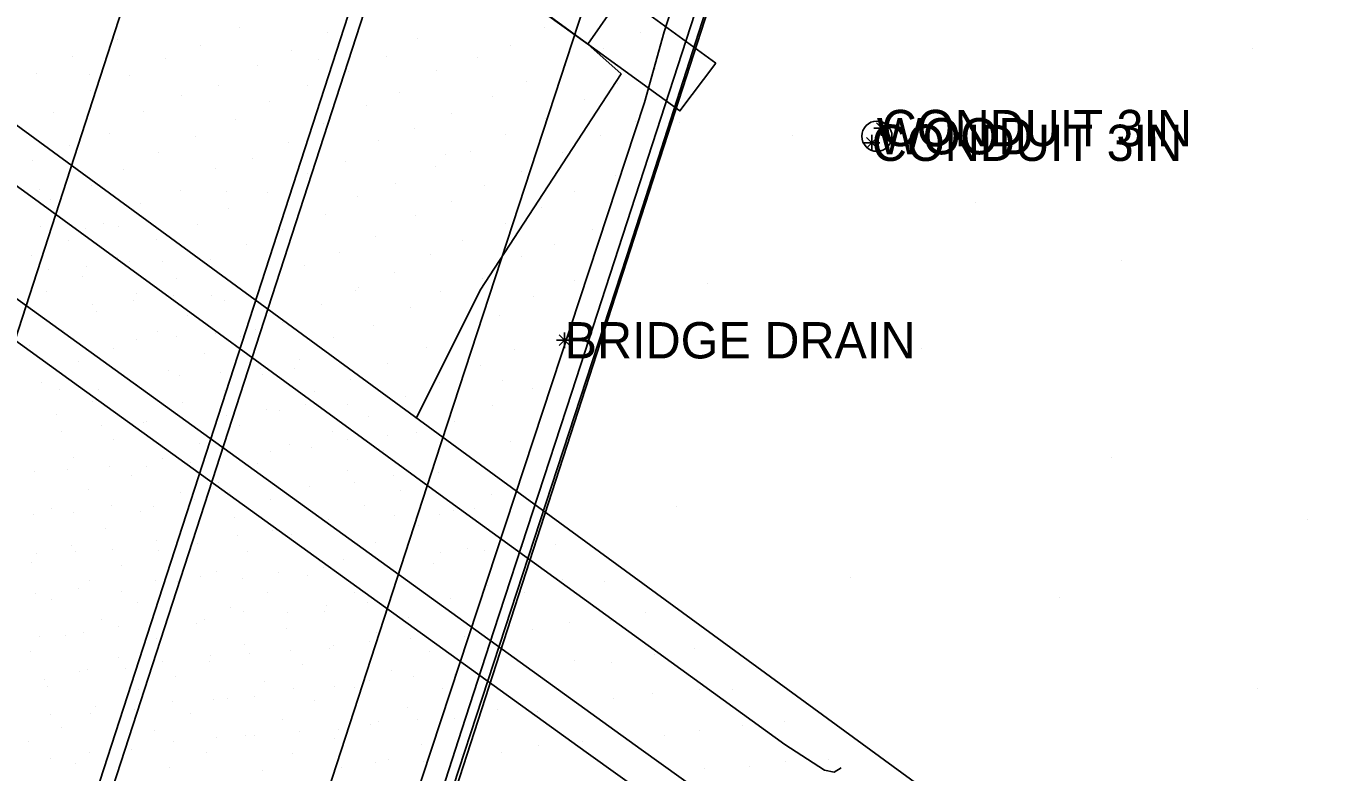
# Model space of a CAD drawing. Extents: x 0 to 1739264, y 0 to 465304.
# Drawn here: x 1738821.1 to 1738885.4, y 464600.2 to 464637.2 of the extents above; entities that cross this region are included whole.
import ezdxf

# ---------------------------------------------------------------- set-up
doc = ezdxf.new("R2010")
doc.units = 0
for name, color, linetype in [('Default', 7, 'Continuous'), ('S_Ground_SpotElevation', 7, 'Continuous'), ('S_Misc_MiscItems', 7, 'Continuous'), ('S_Terrain_Boundary', 7, 'Continuous'), ('S_Terrain_Flow_Arrows', 7, 'Continuous'), ('S_Terrain_Holes', 7, 'Continuous'), ('S_Terrain_Imported_Contours', 7, 'Continuous'), ('S_Terrain_Low_Points', 7, 'Continuous'), ('S_Terrain_Major_Contours_Label', 7, 'Continuous'), ('S_Terrain_Minor_Contours', 7, 'Continuous'), ('S_Terrain_Spots', 7, 'Continuous'), ('S_Terrain_Triangles', 7, 'Continuous'), ('S_Terrain_XSC', 7, 'Continuous'), ('S_Text', 7, 'Continuous'), ('S_Traffic_Posts', 7, 'Continuous')]:
    doc.layers.add(name, color=color, linetype=linetype)

# ---------------------------------------------------------------- blocks, each defined once
blk = doc.blocks.new('POINT_DISPLAY')
at = {"layer": 'Default'}
blk.add_line((0, 0), (0, 0), dxfattribs=at)

msp = doc.modelspace()

# ---------------------------------------------------------------- linework, layer by layer
at = {"layer": 'S_Misc_MiscItems'}
for p, q in [((1738863.757081, 464631.874419), (1738863.232919, 464632.398581)), ((1738863.757081, 464632.398581), (1738863.232919, 464631.874419)), ((1738863.495, 464632.529425), (1738863.495, 464631.743575)), ((1738863.271081, 464631.142519), (1738862.746919, 464631.666681)), ((1738863.271081, 464631.666681), (1738862.746919, 464631.142519)), ((1738863.009, 464631.797525), (1738863.009, 464631.011675)), ((1738863.887925, 464632.1365), (1738863.102075, 464632.1365)), ((1738863.401925, 464631.4046), (1738862.616075, 464631.4046)), ((1738847.785, 464622.004625), (1738847.785, 464621.218775)), ((1738848.177925, 464621.6117), (1738847.392075, 464621.6117)), ((1738848.047081, 464621.349619), (1738847.522919, 464621.873781)), ((1738848.047081, 464621.873781), (1738847.522919, 464621.349619))]:
    msp.add_line(p, q, dxfattribs=at)
at = {"layer": 'S_Terrain_Boundary'}
msp.add_lwpolyline([(1738439.271413, 464900.197601), (1738492.404409, 464861.888198), (1738543.326406, 464825.027297), (1738587.987508, 464792.577201), (1738643.601995, 464752.008903), (1738684.834997, 464722.042197), (1738725.906102, 464692.517997), (1738772.431699, 464658.71659), (1738810.132402, 464631.254401), (1738851.5753, 464601.325202), (1738896.7613, 464568.902991), (1738947.229398, 464532.229499), (1738988.834096, 464501.959205), (1739034.470907, 464468.655585), (1739109.710805, 464413.704902), (1739191.418111, 464354.569221)], dxfattribs=at)
at = {"layer": 'S_Terrain_Flow_Arrows'}
msp.add_lwpolyline([(1738537.8915, 464837.651298), (1738554.679006, 464823.736503), (1738571.817098, 464809.695602), (1738604.832906, 464785.812995), (1738647.717305, 464754.6706), (1738693.440099, 464721.453605), (1738721.065099, 464701.443504), (1738755.298902, 464676.469901), (1738784.46756, 464655.434135), (1738807.545301, 464638.717994), (1738821.158399, 464628.894904), (1738841.6217, 464613.944495), (1738858.6917, 464601.566993), (1738860.6704, 464600.29029), (1738861.1426, 464600.200813), (1738861.4941, 464600.40879)], dxfattribs=at)
at = {"layer": 'S_Terrain_Holes'}
msp.add_lwpolyline([(1738440.753408, 464902.4178), (1738477.708303, 464875.6944), (1738495.304403, 464867.276199), (1738520.483205, 464854.988197), (1738531.014211, 464849.447196), (1738541.85439, 464843.616599), (1738555.182912, 464833.824599), (1738566.262288, 464820.809898), (1738575.120687, 464811.715797), (1738599.964589, 464792.622993), (1738652.316198, 464754.776099), (1738717.522497, 464707.258094), (1738763.349103, 464673.881202), (1738798.761701, 464648.314307), (1738844.3003, 464614.942512), (1738868.1803, 464597.462104), (1738886.0282, 464581.007392), (1738908.3057, 464562.901496), (1738954.7096, 464529.656501), (1739018.291097, 464483.184303), (1739106.594198, 464418.788093), (1739192.640493, 464356.621711)], dxfattribs=at)
at = {"layer": 'S_Terrain_Imported_Contours'}
for points in [[(1739190.423909, 464353.133613), (1739167.420003, 464369.643989), (1739136.08901, 464392.395698), (1739099.705907, 464418.823005), (1739063.097905, 464445.382789), (1739029.015203, 464470.072303), (1738994.960698, 464494.975715), (1738963.306501, 464517.971687), (1738929.921899, 464542.445991), (1738906.520002, 464559.5727), (1738874.1911, 464583.0391), (1738848.8528, 464601.190101), (1738823.7002, 464619.344093), (1738782.379201, 464649.285285), (1738744.080297, 464677.037101), (1738707.677694, 464703.427207), (1738674.247396, 464727.672202), (1738642.1256, 464750.929404), (1738607.146993, 464776.238105), (1738572.1126, 464801.885703), (1738543.106313, 464823.0764), (1738517.901113, 464841.4272), (1738491.543599, 464860.480499), (1738456.809285, 464885.663299)], [(1738861.917132, 464749.554455), (1738852.728099, 464720.865302), (1738834.137899, 464663.640296), (1738810.806299, 464591.494392), (1738798.57878, 464553.775144)], [(1738807.560265, 464547.101191), (1738818.883699, 464581.650611), (1738840.7733, 464649.227912), (1738859.7717, 464707.561698), (1738871.099421, 464743.042961)], [(1738871.2811, 464741.761298), (1738862.9528, 464715.336097), (1738835.861902, 464631.717414), (1738814.1443, 464564.731208), (1738808.177672, 464546.642409)], [(1738816.833754, 464540.526168), (1738828.844899, 464576.996803), (1738841.383399, 464615.664314), (1738851.1298, 464645.487891), (1738867.0642, 464694.79), (1738880.224773, 464736.284008)]]:
    msp.add_lwpolyline(points, dxfattribs=at)
at = {"layer": 'S_Terrain_Low_Points'}
for points in [[(1738882.8352, 464729.589896), (1738865.96384, 464677.988066), (1738852.7233, 464636.911414), (1738851.7415, 464633.401588)], [(1738855.273806, 464635.360066), (1738849.82601, 464639.341633), (1738849.6067, 464639.508537), (1738843.48614, 464643.947537), (1738842.990873, 464644.311317), (1738830.438266, 464653.454034), (1738830.074485, 464653.734539), (1738824.876175, 464657.51796), (1738823.095667, 464655.040075), (1738828.032899, 464651.473037)], [(1738828.032899, 464651.473037), (1738828.923843, 464650.857843), (1738835.002801, 464646.444007), (1738835.226499, 464646.274299), (1738841.568099, 464641.72721), (1738841.7203, 464641.579993), (1738848.058099, 464636.947089), (1738848.372052, 464636.714783), (1738853.500766, 464632.982073), (1738855.273806, 464635.360066)], [(1738848.937102, 464636.293874), (1738850.584337, 464634.827255), (1738843.601699, 464624.089088), (1738840.440747, 464617.770886)], [(1738851.7415, 464633.401588), (1738839.363599, 464595.771888), (1738822.210698, 464542.4672)]]:
    msp.add_lwpolyline(points, dxfattribs=at)
at = {"layer": 'S_Terrain_Major_Contours_Label'}
msp.add_lwpolyline([(1738885.395159, 464732.452095), (1738884.2943, 464729.028999), (1738875.3401, 464701.327995), (1738857.6966, 464646.653999), (1738844.752799, 464606.659614), (1738829.9694, 464560.926002), (1738822.141572, 464536.77828)], dxfattribs=at)
at = {"layer": 'S_Terrain_Minor_Contours'}
for points in [[(1738844.286302, 464607.201361), (1738848.147801, 464619.041197), (1738858.648407, 464651.422155), (1738867.135194, 464677.65191)], [(1738822.502035, 464539.871865), (1738828.574695, 464558.460113), (1738842.68621, 464602.312192), (1738844.286302, 464607.201361)]]:
    msp.add_lwpolyline(points, dxfattribs=at)
at = {"layer": 'S_Terrain_Spots'}
msp.add_lwpolyline([(1738848.937102, 464636.293874), (1738850.584337, 464634.827255), (1738843.601699, 464624.089088), (1738840.440747, 464617.770886)], dxfattribs=at)
at = {"layer": 'S_Terrain_Triangles'}
msp.add_lwpolyline([(1738885.339743, 464732.493165), (1738884.4636, 464729.823402), (1738878.6737, 464712.005698), (1738871.4064, 464689.647605), (1738862.8085, 464662.946113), (1738850.8758, 464625.801398), (1738841.409499, 464596.833595), (1738830.533101, 464562.882606), (1738822.877599, 464539.516792), (1738822.019587, 464536.864414)], dxfattribs=at)
at = {"layer": 'S_Terrain_XSC'}
msp.add_lwpolyline([(1738828.329702, 464651.282111), (1738839.572801, 464643.045295), (1738848.937102, 464636.293874), (1738850.651702, 464638.781989), (1738839.959664, 464646.566968), (1738830.059193, 464653.760598), (1738828.329702, 464651.282111)], dxfattribs=at)
at = {"layer": 'S_Traffic_Posts'}
msp.add_circle((1738863.258, 464631.731), 0.748523, dxfattribs=at)

# ---------------------------------------------------------------- block references
at = {"layer": 'S_Ground_SpotElevation'}
for p in [(1738831.681804, 464637.119804), (1738836.059505, 464636.855278), (1738846.794505, 464637.139519), (1738851.536204, 464636.86248), (1738825.611797, 464636.519096), (1738829.7597, 464636.208671), (1738840.5106, 464636.591972), (1738845.128307, 464636.23571), (1738849.691005, 464636.084709), (1738881.863206, 464636.085003), (1738823.419307, 464635.699516), (1738828.021205, 464635.566704), (1738834.265605, 464635.993706), (1738835.572301, 464635.559301), (1738838.965694, 464635.685478), (1738843.458202, 464635.620293), (1738821.596004, 464634.846123), (1738824.261899, 464634.790685), (1738832.577998, 464635.230705), (1738837.085704, 464634.938286), (1738841.445399, 464634.975822), (1738847.855006, 464635.229973), (1738852.2989, 464635.108208), (1738826.215297, 464634.740227), (1738830.625194, 464634.269096), (1738835.042705, 464634.232719), (1738845.875606, 464634.462211), (1738850.404399, 464634.364372), (1738824.2709, 464633.994682), (1738828.824107, 464633.742119), (1738839.618999, 464633.877006), (1738844.218394, 464633.701103), (1738848.754604, 464633.534782), (1738822.468394, 464632.903801), (1738826.9257, 464632.974419), (1738833.160304, 464633.431084), (1738837.981807, 464633.263603), (1738831.497203, 464632.538383), (1738835.852901, 464632.362114), (1738842.202006, 464632.846123), (1738846.858302, 464632.627922), (1738851.274806, 464632.465813), (1738853.4811, 464632.404699), (1738825.239101, 464631.848686), (1738829.513896, 464631.721489), (1738840.342799, 464632.104912), (1738844.868205, 464631.816582), (1738849.557002, 464631.748405), (1738859.071793, 464631.773968), (1738823.262202, 464631.294792), (1738834.120006, 464631.421379), (1738838.554103, 464631.52642), (1738843.125896, 464630.96331), (1738821.426204, 464630.547294), (1738827.687801, 464630.920891), (1738832.309306, 464630.644096), (1738836.915996, 464630.467827), (1738841.908099, 464630.82221), (1738847.693797, 464630.920402), (1738825.920207, 464630.057487), (1738830.498103, 464630.126396), (1738835.066997, 464629.894585), (1738841.3968, 464630.226189), (1738845.673198, 464629.974296), (1738850.3287, 464629.790886), (1738821.782085, 464629.107488), (1738824.343898, 464629.309318), (1738828.756801, 464629.054985), (1738839.415507, 464629.385979), (1738843.812694, 464629.287224), (1738848.280894, 464629.010918), (1738822.294704, 464628.603203), (1738826.778896, 464628.412895), (1738831.0295, 464628.972692), (1738833.047496, 464628.931023), (1738837.499797, 464628.739982), (1738842.1981, 464628.47393), (1738868.142197, 464628.428082), (1738831.137996, 464628.14019), (1738835.938197, 464627.835014), (1738840.392604, 464627.788689), (1738846.650905, 464628.187309), (1738821.842296, 464627.236608), (1738824.052898, 464627.158086), (1738824.943507, 464627.381889), (1738825.658092, 464627.277685), (1738829.605495, 464627.351799), (1738833.787807, 464627.115288), (1738844.840999, 464627.397026), (1738849.152599, 464627.11663), (1738823.201701, 464626.578728), (1738827.571803, 464626.611626), (1738838.424297, 464626.761406), (1738842.702403, 464626.582329), (1738821.374705, 464625.822319), (1738832.000606, 464626.383171), (1738836.624293, 464625.966484), (1738841.144206, 464625.874504), (1738847.300395, 464626.356377), (1738849.3199, 464625.893286), (1738824.110393, 464625.258489), (1738825.631404, 464625.712028), (1738826.2346, 464625.540807), (1738827.887401, 464625.520788), (1738830.250606, 464625.613274), (1738834.921596, 464625.32769), (1738845.669597, 464625.759209), (1738875.401002, 464625.584881), (1738822.19981, 464625.126897), (1738823.879405, 464624.787224), (1738828.538905, 464624.653007), (1738839.378795, 464624.992424), (1738843.7364, 464624.684013), (1738848.275005, 464624.577324), (1738822.131694, 464624.019218), (1738826.554698, 464623.949577), (1738832.7615, 464624.387016), (1738837.417506, 464624.083488), (1738837.5764, 464624.205511), (1738841.660503, 464624.013725), (1738854.857407, 464624.438397), (1738824.386699, 464623.400213), (1738826.417797, 464623.567999), (1738828.3838, 464623.8299), (1738830.29771, 464623.820898), (1738830.9472, 464623.580986), (1738835.720103, 464623.386406), (1738840.1674, 464623.228081), (1738846.269298, 464623.781486), (1738824.612407, 464623.025322), (1738829.114696, 464622.833122), (1738844.559795, 464622.846428), (1738822.936305, 464622.106621), (1738827.593593, 464622.037712), (1738830.490703, 464621.954107), (1738832.489513, 464622.166601), (1738833.792003, 464622.481071), (1738838.336406, 464622.331474), (1738842.555705, 464622.057793), (1738821.275905, 464621.36602), (1738826.553905, 464621.626287), (1738828.580211, 464621.797399), (1738831.719005, 464621.782402), (1738836.320705, 464621.768791), (1738825.417293, 464621.191704), (1738829.949, 464620.936821), (1738834.630901, 464620.662895), (1738840.936397, 464621.258171), (1738845.320201, 464621.131889), (1738865.490693, 464621.189861), (1738823.686595, 464620.573601), (1738828.147502, 464620.132194), (1738830.744701, 464620.035192), (1738832.739299, 464620.211401), (1738834.39439, 464620.224798), (1738839.020305, 464620.478386), (1738843.631908, 464620.356926), (1738821.858195, 464619.521599), (1738826.587306, 464619.42968), (1738828.728313, 464619.874487), (1738832.834193, 464619.904228), (1738837.200404, 464619.677421), (1738841.593104, 464619.533501), (1738844.7116, 464619.622686), (1738822.755993, 464619.182684), (1738824.699993, 464619.163305), (1738830.923595, 464619.132805), (1738835.369395, 464619.06591), (1738839.917094, 464618.814384), (1738846.205897, 464619.200798), (1738824.404994, 464618.56353), (1738828.869899, 464618.517692), (1738833.019695, 464618.1872), (1738833.644206, 464618.147026), (1738834.956493, 464618.445684), (1738837.044506, 464618.421301), (1738844.225001, 464618.375908), (1738822.614604, 464617.947807), (1738826.929607, 464617.552496), (1738827.081905, 464617.582512), (1738831.033794, 464617.886083), (1738838.059703, 464617.830376), (1738842.347301, 464617.576286), (1738822.840496, 464617.10169), (1738824.8502, 464617.394292), (1738831.682506, 464617.409111), (1738836.282603, 464617.077324), (1738839.025402, 464616.881384), (1738840.4575, 464617.05999), (1738825.422603, 464616.695915), (1738829.672404, 464616.515983), (1738834.136607, 464616.438286), (1738835.234813, 464616.283102), (1738837.018108, 464616.684393), (1738838.797404, 464616.152885), (1738845.116496, 464616.577812), (1738823.4575, 464615.814323), (1738827.846995, 464615.754082), (1738829.247692, 464615.547903), (1738832.5852, 464615.522514), (1738833.20631, 464616.120321), (1738843.167903, 464615.753776), (1738874.906693, 464615.779278), (1738821.523296, 464615.11132), (1738823.173412, 464615.1993), (1738825.223308, 464615.331106), (1738826.3222, 464614.904472), (1738827.064495, 464615.372518), (1738837.012294, 464615.164787), (1738839.294689, 464614.893911), (1738841.231487, 464615.096029), (1738841.553599, 464615.077507), (1738845.734294, 464615.007194), (1738824.211803, 464614.231499), (1738830.632198, 464614.579277), (1738835.161006, 464614.338188), (1738837.369304, 464614.572012), (1738828.739299, 464614.061699), (1738829.43391, 464613.701406), (1738831.196392, 464614.073202), (1738833.231502, 464613.692985), (1738839.663997, 464614.156975), (1738844.139598, 464613.968193), (1738821.489696, 464612.961416), (1738822.346995, 464613.275383), (1738823.455791, 464613.071401), (1738825.340496, 464613.414907), (1738826.791698, 464613.119987), (1738827.433513, 464613.386404), (1738837.884807, 464613.398674), (1738839.343395, 464612.930929), (1738841.610393, 464612.955709), (1738842.299907, 464613.178825), (1738843.339092, 464613.283315), (1738853.349503, 464613.353985), (1738825.043193, 464612.279472), (1738831.408107, 464612.82769), (1738836.077998, 464612.738884), (1738840.528606, 464612.448784), (1738884.585999, 464612.70158), (1738827.567791, 464611.681203), (1738829.514598, 464612.225517), (1738831.58781, 464611.937002), (1738833.291088, 464612.201406), (1738834.236705, 464611.963005), (1738844.7727, 464612.14489), (1738821.60841, 464611.056112), (1738823.370799, 464611.437675), (1738823.576488, 464611.160116), (1738825.363201, 464611.222005), (1738827.661906, 464611.181206), (1738829.591106, 464611.535513), (1738832.076701, 464611.157707), (1738838.394694, 464611.579094), (1738841.638988, 464611.100118), (1738842.974696, 464611.29583), (1738843.804393, 464611.176626), (1738845.715893, 464611.390524), (1738847.312908, 464611.463613), (1738821.387294, 464610.583), (1738825.822597, 464610.42968), (1738836.809596, 464610.736809), (1738841.293605, 464610.542107), (1738829.726391, 464609.913412), (1738830.561305, 464610.158012), (1738831.832103, 464609.812002), (1738833.633098, 464610.119924), (1738835.044398, 464609.951774), (1738835.816204, 464610.335409), (1738839.510707, 464609.7976), (1738847.694408, 464609.743124), (1738861.956406, 464609.83189), (1738821.586101, 464609.078817), (1738823.710308, 464609.304525), (1738824.258006, 464609.690605), (1738825.826091, 464609.154226), (1738827.510387, 464609.69042), (1738828.602794, 464609.649528), (1738833.043101, 464609.083916), (1738837.372798, 464609.111626), (1738843.867901, 464609.233511), (1738843.946208, 464609.473808), (1738845.798687, 464609.093313), (1738849.786388, 464609.654317), (1738822.385493, 464608.751579), (1738826.608394, 464608.591789), (1738835.974498, 464608.451528), (1738838.005108, 464608.598104), (1738842.125102, 464608.804191), (1738872.319093, 464608.845806), (1738824.8269, 464607.785271), (1738829.93211, 464607.777517), (1738831.253703, 464608.338188), (1738831.855602, 464608.14681), (1738834.056194, 464608.089803), (1738835.876094, 464608.172722), (1738840.068507, 464607.84539), (1738851.78651, 464608.107412), (1738825.660503, 464607.397024), (1738827.991314, 464607.677908), (1738829.535899, 464607.573601), (1738834.011394, 464607.295891), (1738838.485606, 464607.130485), (1738846.187511, 464607.254415), (1738848.050914, 464607.608114), (1738850.047405, 464607.691518), (1738821.767498, 464606.909628), (1738823.051707, 464606.957695), (1738823.925792, 464607.110403), (1738827.558604, 464606.822624), (1738831.9369, 464606.50518), (1738838.094494, 464606.689413), (1738840.135601, 464606.827016), (1738842.839305, 464606.914604), (1738821.298106, 464606.161674), (1738825.659999, 464605.894585), (1738830.244395, 464605.966179), (1738832.155407, 464606.061422), (1738834.210186, 464606.219106), (1738836.122204, 464606.333303), (1738836.3352, 464606.485283), (1738841.103496, 464606.165214), (1738852.249492, 464606.02651), (1738854.225597, 464606.342519), (1738824.161388, 464605.268423), (1738826.047893, 464605.342703), (1738827.861492, 464605.672506), (1738830.208996, 464605.6816), (1738834.813197, 464605.527397), (1738839.195705, 464605.220329), (1738844.330486, 464605.204122), (1738848.272411, 464605.735616), (1738850.116497, 464605.657308), (1738822.017193, 464604.8113), (1738823.738597, 464605.170097), (1738828.531306, 464604.944694), (1738832.916804, 464604.67559), (1738838.136608, 464604.745199), (1738840.294903, 464604.944418), (1738842.330211, 464605.020925), (1738822.172206, 464604.425102), (1738826.679896, 464604.281731), (1738832.417492, 464603.951009), (1738834.345806, 464604.321401), (1738836.380413, 464604.459005), (1738837.352107, 464604.376579), (1738841.730601, 464604.333), (1738852.150493, 464604.094625), (1738854.490093, 464604.301199), (1738856.085796, 464604.28301), (1738882.125001, 464604.368389), (1738824.544093, 464603.457329), (1738826.492595, 464603.322012), (1738828.366893, 464603.678304), (1738830.398296, 464603.822713), (1738831.059993, 464603.82592), (1738835.382594, 464603.751884), (1738840.005595, 464603.392204), (1738844.465191, 464603.313924), (1738850.204815, 464603.864614), (1738822.302501, 464603.037313), (1738824.274791, 464603.113699), (1738829.241206, 464603.081474), (1738833.786693, 464602.82653), (1738838.57011, 464602.713613), (1738840.521404, 464602.817922), (1738842.327404, 464602.853109), (1738846.444896, 464603.187521), (1738858.663891, 464602.718801), (1738822.839305, 464602.403374), (1738827.488505, 464602.26281), (1738831.962794, 464602.03521), (1738832.435009, 464602.002218), (1738834.628216, 464602.217916), (1738836.603191, 464602.323202), (1738838.156505, 464602.554191), (1738852.754589, 464601.990316), (1738854.47871, 464602.281118), (1738856.607799, 464602.507406), (1738821.223598, 464601.724724), (1738825.389293, 464601.699028), (1738828.424205, 464601.731619), (1738830.532299, 464601.916311), (1738836.394694, 464601.844719), (1738840.695003, 464601.588005), (1738846.509014, 464601.497427), (1738848.693706, 464601.72402), (1738822.333294, 464600.869527), (1738824.250896, 464601.194021), (1738826.313305, 464601.317403), (1738830.025096, 464601.173881), (1738834.297893, 464601.130607), (1738839.049907, 464600.805229), (1738840.7989, 464600.718008), (1738842.674602, 464601.05422), (1738844.664592, 464601.172903), (1738858.750286, 464600.723501), (1738860.861492, 464600.843526), (1738823.555995, 464600.64019), (1738828.2131, 464600.406975), (1738832.807796, 464600.300529), (1738836.752086, 464600.442526), (1738838.416301, 464600.683706), (1738854.701214, 464600.386221), (1738856.926189, 464600.471304)]:
    msp.add_blockref('POINT_DISPLAY', p, dxfattribs=at)

# ---------------------------------------------------------------- texts
at = {"layer": 'S_Text'}
for s, p in [('CONDUIT 3IN', (1738863.495, 464631.2365)), ('CONDUIT 3IN', (1738863.009, 464630.5046)), ('WOOD', (1738863.258, 464630.831)), ('BRIDGE DRAIN', (1738847.785, 464620.7117))]:
    msp.add_text(s, height=1.8, dxfattribs=at).set_placement(p)

doc.saveas('drawing.dxf')
